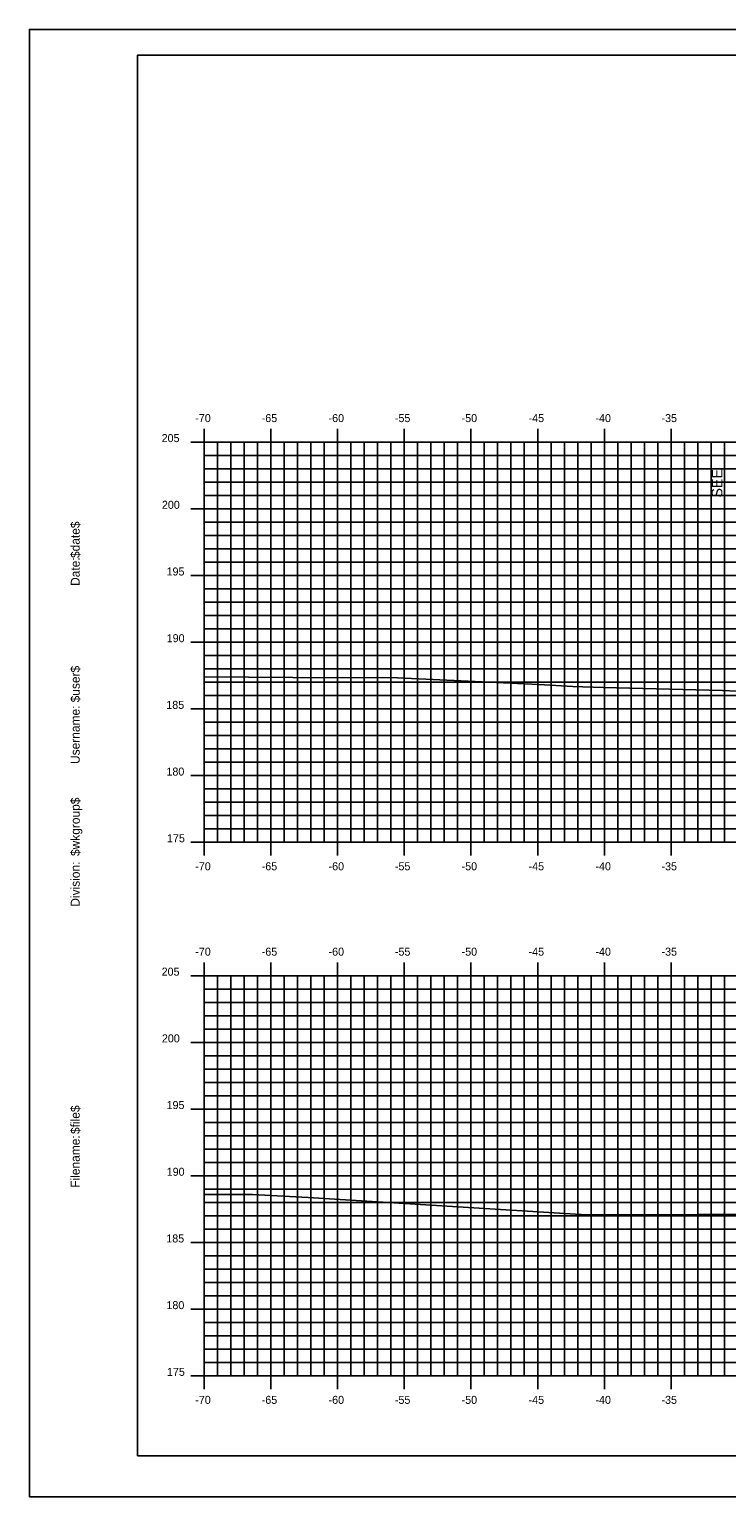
# Model space of a CAD drawing. Extents: x 1724183 to 1724355, y 459560 to 459670.
# Drawn here: x 1724183.1 to 1724235.4, y 459559.6 to 459669.6 of the extents above; entities that cross this region are included whole.
import ezdxf

# ---------------------------------------------------------------- set-up
doc = ezdxf.new("R2010")
doc.units = 0
for name, color, linetype in [('ANNOTATION', 7, 'Continuous'), ('BORDER', 7, 'Continuous'), ('H_V ANNOTATION', 7, 'Continuous'), ('MAJOR', 7, 'Continuous'), ('MINOR', 7, 'Continuous'), ('PLOT BOUNDARY', 7, 'Continuous'), ('S_Roadway_Centerline', 7, 'Continuous')]:
    doc.layers.add(name, color=color, linetype=linetype)

msp = doc.modelspace()

# ---------------------------------------------------------------- linework, layer by layer
at = {"layer": 'BORDER'}
msp.add_lwpolyline([(1724191.23, 459562.61), (1724351.23, 459562.61), (1724351.23, 459667.61), (1724191.23, 459667.61)], close=True, dxfattribs=at)
at = {"layer": 'MAJOR'}
for p, q in [((1724196.23, 459639.61), (1724196.23, 459638.61)), ((1724201.23, 459639.61), (1724201.23, 459638.61)), ((1724206.23, 459639.61), (1724206.23, 459638.61)), ((1724211.23, 459639.61), (1724211.23, 459638.61)), ((1724216.23, 459639.61), (1724216.23, 459638.61)), ((1724221.23, 459639.61), (1724221.23, 459638.61)), ((1724226.23, 459639.61), (1724226.23, 459638.61)), ((1724231.23, 459639.61), (1724231.23, 459638.61)), ((1724195.23, 459638.61), (1724196.23, 459638.61)), ((1724196.23, 459638.61), (1724336.23, 459638.61)), ((1724196.23, 459608.61), (1724196.23, 459638.61)), ((1724196.23, 459608.61), (1724196.23, 459638.61)), ((1724196.23, 459638.61), (1724336.23, 459638.61)), ((1724201.23, 459608.61), (1724201.23, 459638.61)), ((1724206.23, 459608.61), (1724206.23, 459638.61)), ((1724211.23, 459608.61), (1724211.23, 459638.61)), ((1724216.23, 459608.61), (1724216.23, 459638.61)), ((1724221.23, 459608.61), (1724221.23, 459638.61)), ((1724226.23, 459608.61), (1724226.23, 459638.61)), ((1724231.23, 459608.61), (1724231.23, 459638.61)), ((1724195.23, 459633.61), (1724196.23, 459633.61)), ((1724196.23, 459633.61), (1724336.23, 459633.61)), ((1724195.23, 459628.61), (1724196.23, 459628.61)), ((1724196.23, 459628.61), (1724336.23, 459628.61)), ((1724195.23, 459623.61), (1724196.23, 459623.61)), ((1724196.23, 459623.61), (1724336.23, 459623.61)), ((1724195.23, 459618.61), (1724196.23, 459618.61)), ((1724196.23, 459618.61), (1724336.23, 459618.61)), ((1724195.23, 459613.61), (1724196.23, 459613.61)), ((1724196.23, 459613.61), (1724336.23, 459613.61)), ((1724195.23, 459608.61), (1724196.23, 459608.61)), ((1724196.23, 459608.61), (1724336.23, 459608.61)), ((1724196.23, 459608.61), (1724336.23, 459608.61)), ((1724196.23, 459607.61), (1724196.23, 459608.61)), ((1724201.23, 459607.61), (1724201.23, 459608.61)), ((1724206.23, 459607.61), (1724206.23, 459608.61)), ((1724211.23, 459607.61), (1724211.23, 459608.61)), ((1724216.23, 459607.61), (1724216.23, 459608.61)), ((1724221.23, 459607.61), (1724221.23, 459608.61)), ((1724226.23, 459607.61), (1724226.23, 459608.61)), ((1724231.23, 459607.61), (1724231.23, 459608.61)), ((1724196.23, 459599.61), (1724196.23, 459598.61)), ((1724201.23, 459599.61), (1724201.23, 459598.61)), ((1724206.23, 459599.61), (1724206.23, 459598.61)), ((1724211.23, 459599.61), (1724211.23, 459598.61)), ((1724216.23, 459599.61), (1724216.23, 459598.61)), ((1724221.23, 459599.61), (1724221.23, 459598.61)), ((1724226.23, 459599.61), (1724226.23, 459598.61)), ((1724231.23, 459599.61), (1724231.23, 459598.61)), ((1724195.23, 459598.61), (1724196.23, 459598.61)), ((1724196.23, 459598.61), (1724336.23, 459598.61)), ((1724196.23, 459568.61), (1724196.23, 459598.61)), ((1724196.23, 459568.61), (1724196.23, 459598.61)), ((1724196.23, 459598.61), (1724336.23, 459598.61)), ((1724201.23, 459568.61), (1724201.23, 459598.61)), ((1724206.23, 459568.61), (1724206.23, 459598.61)), ((1724211.23, 459568.61), (1724211.23, 459598.61)), ((1724216.23, 459568.61), (1724216.23, 459598.61)), ((1724221.23, 459568.61), (1724221.23, 459598.61)), ((1724226.23, 459568.61), (1724226.23, 459598.61)), ((1724231.23, 459568.61), (1724231.23, 459598.61)), ((1724195.23, 459593.61), (1724196.23, 459593.61)), ((1724196.23, 459593.61), (1724336.23, 459593.61)), ((1724195.23, 459588.61), (1724196.23, 459588.61)), ((1724196.23, 459588.61), (1724336.23, 459588.61)), ((1724195.23, 459583.61), (1724196.23, 459583.61)), ((1724196.23, 459583.61), (1724336.23, 459583.61)), ((1724195.23, 459578.61), (1724196.23, 459578.61)), ((1724196.23, 459578.61), (1724336.23, 459578.61)), ((1724195.23, 459573.61), (1724196.23, 459573.61)), ((1724196.23, 459573.61), (1724336.23, 459573.61)), ((1724195.23, 459568.61), (1724196.23, 459568.61)), ((1724196.23, 459568.61), (1724336.23, 459568.61)), ((1724196.23, 459568.61), (1724336.23, 459568.61)), ((1724196.23, 459567.61), (1724196.23, 459568.61)), ((1724201.23, 459567.61), (1724201.23, 459568.61)), ((1724206.23, 459567.61), (1724206.23, 459568.61)), ((1724211.23, 459567.61), (1724211.23, 459568.61)), ((1724216.23, 459567.61), (1724216.23, 459568.61)), ((1724221.23, 459567.61), (1724221.23, 459568.61)), ((1724226.23, 459567.61), (1724226.23, 459568.61)), ((1724231.23, 459567.61), (1724231.23, 459568.61))]:
    msp.add_line(p, q, dxfattribs=at)
at = {"layer": 'MINOR'}
for p, q in [((1724197.23, 459608.61), (1724197.23, 459638.61)), ((1724198.23, 459608.61), (1724198.23, 459638.61)), ((1724199.23, 459608.61), (1724199.23, 459638.61)), ((1724200.23, 459608.61), (1724200.23, 459638.61)), ((1724202.23, 459608.61), (1724202.23, 459638.61)), ((1724203.23, 459608.61), (1724203.23, 459638.61)), ((1724204.23, 459608.61), (1724204.23, 459638.61)), ((1724205.23, 459608.61), (1724205.23, 459638.61)), ((1724207.23, 459608.61), (1724207.23, 459638.61)), ((1724208.23, 459608.61), (1724208.23, 459638.61)), ((1724209.23, 459608.61), (1724209.23, 459638.61)), ((1724210.23, 459608.61), (1724210.23, 459638.61)), ((1724212.23, 459608.61), (1724212.23, 459638.61)), ((1724213.23, 459608.61), (1724213.23, 459638.61)), ((1724214.23, 459608.61), (1724214.23, 459638.61)), ((1724215.23, 459608.61), (1724215.23, 459638.61)), ((1724217.23, 459608.61), (1724217.23, 459638.61)), ((1724218.23, 459608.61), (1724218.23, 459638.61)), ((1724219.23, 459608.61), (1724219.23, 459638.61)), ((1724220.23, 459608.61), (1724220.23, 459638.61)), ((1724222.23, 459608.61), (1724222.23, 459638.61)), ((1724223.23, 459608.61), (1724223.23, 459638.61)), ((1724224.23, 459608.61), (1724224.23, 459638.61)), ((1724225.23, 459608.61), (1724225.23, 459638.61)), ((1724227.23, 459608.61), (1724227.23, 459638.61)), ((1724228.23, 459608.61), (1724228.23, 459638.61)), ((1724229.23, 459608.61), (1724229.23, 459638.61)), ((1724230.23, 459608.61), (1724230.23, 459638.61)), ((1724232.23, 459608.61), (1724232.23, 459638.61)), ((1724233.23, 459608.61), (1724233.23, 459638.61)), ((1724234.23, 459608.61), (1724234.23, 459638.61)), ((1724235.23, 459608.61), (1724235.23, 459638.61)), ((1724196.23, 459637.61), (1724336.23, 459637.61)), ((1724196.23, 459637.61), (1724197.23, 459637.61)), ((1724196.23, 459636.61), (1724336.23, 459636.61)), ((1724196.23, 459636.61), (1724197.23, 459636.61)), ((1724196.23, 459635.61), (1724336.23, 459635.61)), ((1724196.23, 459635.61), (1724197.23, 459635.61)), ((1724196.23, 459634.61), (1724336.23, 459634.61)), ((1724196.23, 459634.61), (1724197.23, 459634.61)), ((1724196.23, 459632.61), (1724336.23, 459632.61)), ((1724196.23, 459632.61), (1724197.23, 459632.61)), ((1724196.23, 459631.61), (1724336.23, 459631.61)), ((1724196.23, 459631.61), (1724197.23, 459631.61)), ((1724196.23, 459630.61), (1724336.23, 459630.61)), ((1724196.23, 459630.61), (1724197.23, 459630.61)), ((1724196.23, 459629.61), (1724336.23, 459629.61)), ((1724196.23, 459629.61), (1724197.23, 459629.61)), ((1724196.23, 459627.61), (1724336.23, 459627.61)), ((1724196.23, 459627.61), (1724197.23, 459627.61)), ((1724196.23, 459626.61), (1724336.23, 459626.61)), ((1724196.23, 459626.61), (1724197.23, 459626.61)), ((1724196.23, 459625.61), (1724336.23, 459625.61)), ((1724196.23, 459625.61), (1724197.23, 459625.61)), ((1724196.23, 459624.61), (1724336.23, 459624.61)), ((1724196.23, 459624.61), (1724197.23, 459624.61)), ((1724196.23, 459622.61), (1724336.23, 459622.61)), ((1724196.23, 459622.61), (1724197.23, 459622.61)), ((1724196.23, 459621.61), (1724336.23, 459621.61)), ((1724196.23, 459621.61), (1724197.23, 459621.61)), ((1724196.23, 459620.61), (1724336.23, 459620.61)), ((1724196.23, 459620.61), (1724197.23, 459620.61)), ((1724196.23, 459619.61), (1724336.23, 459619.61)), ((1724196.23, 459619.61), (1724197.23, 459619.61)), ((1724196.23, 459617.61), (1724336.23, 459617.61)), ((1724196.23, 459617.61), (1724197.23, 459617.61)), ((1724196.23, 459616.61), (1724336.23, 459616.61)), ((1724196.23, 459616.61), (1724197.23, 459616.61)), ((1724196.23, 459615.61), (1724336.23, 459615.61)), ((1724196.23, 459615.61), (1724197.23, 459615.61)), ((1724196.23, 459614.61), (1724336.23, 459614.61)), ((1724196.23, 459614.61), (1724197.23, 459614.61)), ((1724196.23, 459612.61), (1724336.23, 459612.61)), ((1724196.23, 459612.61), (1724197.23, 459612.61)), ((1724196.23, 459611.61), (1724336.23, 459611.61)), ((1724196.23, 459611.61), (1724197.23, 459611.61)), ((1724196.23, 459610.61), (1724336.23, 459610.61)), ((1724196.23, 459610.61), (1724197.23, 459610.61)), ((1724196.23, 459609.61), (1724336.23, 459609.61)), ((1724196.23, 459609.61), (1724197.23, 459609.61)), ((1724196.23, 459597.61), (1724336.23, 459597.61)), ((1724196.23, 459597.61), (1724197.23, 459597.61)), ((1724197.23, 459568.61), (1724197.23, 459598.61)), ((1724198.23, 459568.61), (1724198.23, 459598.61)), ((1724199.23, 459568.61), (1724199.23, 459598.61)), ((1724200.23, 459568.61), (1724200.23, 459598.61)), ((1724202.23, 459568.61), (1724202.23, 459598.61)), ((1724203.23, 459568.61), (1724203.23, 459598.61)), ((1724204.23, 459568.61), (1724204.23, 459598.61)), ((1724205.23, 459568.61), (1724205.23, 459598.61)), ((1724207.23, 459568.61), (1724207.23, 459598.61)), ((1724208.23, 459568.61), (1724208.23, 459598.61)), ((1724209.23, 459568.61), (1724209.23, 459598.61)), ((1724210.23, 459568.61), (1724210.23, 459598.61)), ((1724212.23, 459568.61), (1724212.23, 459598.61)), ((1724213.23, 459568.61), (1724213.23, 459598.61)), ((1724214.23, 459568.61), (1724214.23, 459598.61)), ((1724215.23, 459568.61), (1724215.23, 459598.61)), ((1724217.23, 459568.61), (1724217.23, 459598.61)), ((1724218.23, 459568.61), (1724218.23, 459598.61)), ((1724219.23, 459568.61), (1724219.23, 459598.61)), ((1724220.23, 459568.61), (1724220.23, 459598.61)), ((1724222.23, 459568.61), (1724222.23, 459598.61)), ((1724223.23, 459568.61), (1724223.23, 459598.61)), ((1724224.23, 459568.61), (1724224.23, 459598.61)), ((1724225.23, 459568.61), (1724225.23, 459598.61)), ((1724227.23, 459568.61), (1724227.23, 459598.61)), ((1724228.23, 459568.61), (1724228.23, 459598.61)), ((1724229.23, 459568.61), (1724229.23, 459598.61)), ((1724230.23, 459568.61), (1724230.23, 459598.61)), ((1724232.23, 459568.61), (1724232.23, 459598.61)), ((1724233.23, 459568.61), (1724233.23, 459598.61)), ((1724234.23, 459568.61), (1724234.23, 459598.61)), ((1724235.23, 459568.61), (1724235.23, 459598.61)), ((1724196.23, 459596.61), (1724336.23, 459596.61)), ((1724196.23, 459596.61), (1724197.23, 459596.61)), ((1724196.23, 459595.61), (1724336.23, 459595.61)), ((1724196.23, 459595.61), (1724197.23, 459595.61)), ((1724196.23, 459594.61), (1724336.23, 459594.61)), ((1724196.23, 459594.61), (1724197.23, 459594.61)), ((1724196.23, 459592.61), (1724336.23, 459592.61)), ((1724196.23, 459592.61), (1724197.23, 459592.61)), ((1724196.23, 459591.61), (1724336.23, 459591.61)), ((1724196.23, 459591.61), (1724197.23, 459591.61)), ((1724196.23, 459590.61), (1724336.23, 459590.61)), ((1724196.23, 459590.61), (1724197.23, 459590.61)), ((1724196.23, 459589.61), (1724336.23, 459589.61)), ((1724196.23, 459589.61), (1724197.23, 459589.61)), ((1724196.23, 459587.61), (1724336.23, 459587.61)), ((1724196.23, 459587.61), (1724197.23, 459587.61)), ((1724196.23, 459586.61), (1724336.23, 459586.61)), ((1724196.23, 459586.61), (1724197.23, 459586.61)), ((1724196.23, 459585.61), (1724336.23, 459585.61)), ((1724196.23, 459585.61), (1724197.23, 459585.61)), ((1724196.23, 459584.61), (1724336.23, 459584.61)), ((1724196.23, 459584.61), (1724197.23, 459584.61)), ((1724196.23, 459582.61), (1724336.23, 459582.61)), ((1724196.23, 459582.61), (1724197.23, 459582.61)), ((1724196.23, 459581.61), (1724336.23, 459581.61)), ((1724196.23, 459581.61), (1724197.23, 459581.61)), ((1724196.23, 459580.61), (1724336.23, 459580.61)), ((1724196.23, 459580.61), (1724197.23, 459580.61)), ((1724196.23, 459579.61), (1724336.23, 459579.61)), ((1724196.23, 459579.61), (1724197.23, 459579.61)), ((1724196.23, 459577.61), (1724336.23, 459577.61)), ((1724196.23, 459577.61), (1724197.23, 459577.61)), ((1724196.23, 459576.61), (1724336.23, 459576.61)), ((1724196.23, 459576.61), (1724197.23, 459576.61)), ((1724196.23, 459575.61), (1724336.23, 459575.61)), ((1724196.23, 459575.61), (1724197.23, 459575.61)), ((1724196.23, 459574.61), (1724336.23, 459574.61)), ((1724196.23, 459574.61), (1724197.23, 459574.61)), ((1724196.23, 459572.61), (1724336.23, 459572.61)), ((1724196.23, 459572.61), (1724197.23, 459572.61)), ((1724196.23, 459571.61), (1724336.23, 459571.61)), ((1724196.23, 459571.61), (1724197.23, 459571.61)), ((1724196.23, 459570.61), (1724336.23, 459570.61)), ((1724196.23, 459570.61), (1724197.23, 459570.61)), ((1724196.23, 459569.61), (1724336.23, 459569.61)), ((1724196.23, 459569.61), (1724197.23, 459569.61))]:
    msp.add_line(p, q, dxfattribs=at)
at = {"layer": 'PLOT BOUNDARY'}
msp.add_lwpolyline([(1724183.14, 459559.55), (1724353.14, 459559.55), (1724353.14, 459669.55), (1724183.14, 459669.55)], close=True, dxfattribs=at)
at = {"layer": 'S_Roadway_Centerline'}
for points in [[(1724196.23, 459621.01), (1724202.87, 459620.97), (1724210.73, 459620.93), (1724221.32, 459620.44), (1724223.87, 459620.3), (1724226.15, 459620.21), (1724235.09, 459620), (1724244.6, 459619.56), (1724248.06, 459619.5), (1724258.68, 459619.37), (1724270.2, 459618.67), (1724270.63, 459618.66), (1724271.14, 459618.64), (1724291.82, 459618.31), (1724294.57, 459618.28), (1724312.67, 459618.11), (1724315.73, 459618.02), (1724319.16, 459618.01), (1724334.32, 459617.92), (1724336.23, 459617.88)], [(1724196.23, 459582.21), (1724199.86, 459582.21), (1724204.03, 459581.98), (1724224.07, 459580.72), (1724224.93, 459580.68), (1724225.67, 459580.68), (1724240.81, 459580.73), (1724247.35, 459580.74), (1724247.69, 459580.74), (1724248.09, 459580.7), (1724259.98, 459579.47), (1724268.97, 459579.48), (1724274.27, 459579.41), (1724283.45, 459579.01), (1724291.81, 459578.76), (1724298.81, 459578.69), (1724312.8, 459578.43), (1724323.48, 459578.03), (1724334.38, 459577.81), (1724336.23, 459577.79)]]:
    msp.add_lwpolyline(points, dxfattribs=at)

# ---------------------------------------------------------------- texts
at = {"layer": 'ANNOTATION'}
msp.add_text('SEE', height=0.8, rotation=90, dxfattribs=at).set_placement((1724235.07, 459634.45))
at = {"layer": 'BORDER'}
for s, p in [('$date$', (1724186.91, 459629.92)), ('Date:', (1724186.91, 459627.83)), ('$user$', (1724186.91, 459619.1)), ('Username:', (1724186.91, 459614.48)), ('$wkgroup$', (1724186.91, 459607.58)), ('Division:', (1724186.91, 459603.78)), ('$file$', (1724186.91, 459586.74)), ('Filename:', (1724186.91, 459582.71))]:
    msp.add_text(s, height=0.67, rotation=90, dxfattribs=at).set_placement(p)
at = {"layer": 'H_V ANNOTATION'}
for s, p in [('-70', (1724195.57, 459640.11)), ('-65', (1724200.55, 459640.11)), ('-60', (1724205.56, 459640.11)), ('-55', (1724210.53, 459640.11)), ('-50', (1724215.53, 459640.11)), ('-45', (1724220.55, 459640.11)), ('-40', (1724225.56, 459640.11)), ('-35', (1724230.51, 459640.11)), ('205', (1724193.05, 459638.61)), ('200', (1724193.07, 459633.61)), ('195', (1724193.42, 459628.61)), ('190', (1724193.43, 459623.61)), ('185', (1724193.4, 459618.61)), ('180', (1724193.41, 459613.61)), ('175', (1724193.45, 459608.61)), ('-70', (1724195.57, 459606.51)), ('-65', (1724200.55, 459606.51)), ('-60', (1724205.56, 459606.51)), ('-55', (1724210.53, 459606.51)), ('-50', (1724215.53, 459606.51)), ('-45', (1724220.55, 459606.51)), ('-40', (1724225.56, 459606.51)), ('-35', (1724230.51, 459606.51)), ('-70', (1724195.57, 459600.11)), ('-65', (1724200.55, 459600.11)), ('-60', (1724205.56, 459600.11)), ('-55', (1724210.53, 459600.11)), ('-50', (1724215.53, 459600.11)), ('-45', (1724220.55, 459600.11)), ('-40', (1724225.56, 459600.11)), ('-35', (1724230.51, 459600.11)), ('205', (1724193.05, 459598.61)), ('200', (1724193.07, 459593.61)), ('195', (1724193.42, 459588.61)), ('190', (1724193.43, 459583.61)), ('185', (1724193.4, 459578.61)), ('180', (1724193.41, 459573.61)), ('175', (1724193.45, 459568.61)), ('-70', (1724195.57, 459566.51)), ('-65', (1724200.55, 459566.51)), ('-60', (1724205.56, 459566.51)), ('-55', (1724210.53, 459566.51)), ('-50', (1724215.53, 459566.51)), ('-45', (1724220.55, 459566.51)), ('-40', (1724225.56, 459566.51)), ('-35', (1724230.51, 459566.51))]:
    msp.add_text(s, height=0.6, dxfattribs=at).set_placement(p)
at = {"layer": 'MAJOR'}
for p in [(1724196.23, 459608.61), (1724196.23, 459568.61)]:
    msp.add_text('-', height=0.006, dxfattribs=at).set_placement(p)

doc.saveas('drawing.dxf')
